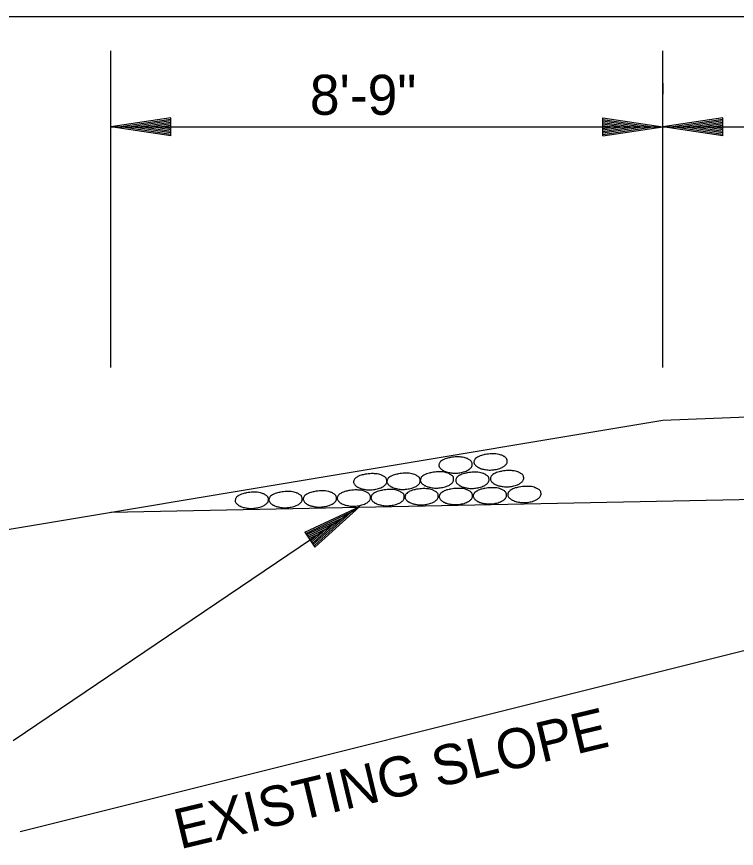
# Model space of a CAD drawing. Extents: x 634177 to 635904, y 289936 to 290970.
# Drawn here: x 635820.98 to 635831.78, y 290605.38 to 290617.85 of the extents above; entities that cross this region are included whole.
import ezdxf

# ---------------------------------------------------------------- set-up
doc = ezdxf.new("R2010")
doc.units = 0
doc.layers.add('Default', color=7, linetype='Continuous')

msp = doc.modelspace()

# ---------------------------------------------------------------- linework, layer by layer
at = {"layer": 'Default'}
for p, q in [((635808.678, 290617.846), (635838.678, 290617.846)), ((635822.398, 290612.588), (635822.398, 290617.336)), ((635830.678, 290612.588), (635830.678, 290617.336)), ((635830.679, 290616.686), (635830.679, 290616.848)), ((635823.298, 290616.328), (635822.398, 290616.193)), ((635823.298, 290616.306), (635822.548, 290616.193)), ((635823.298, 290616.058), (635823.298, 290616.328)), ((635829.778, 290616.328), (635830.678, 290616.193)), ((635829.778, 290616.058), (635829.778, 290616.328)), ((635829.778, 290616.306), (635830.528, 290616.193)), ((635831.578, 290616.328), (635830.678, 290616.193)), ((635831.578, 290616.306), (635830.828, 290616.193)), ((635831.578, 290616.058), (635831.578, 290616.328)), ((635822.398, 290616.193), (635838.678, 290616.193)), ((635823.298, 290616.058), (635822.398, 290616.193)), ((635823.298, 290616.081), (635822.548, 290616.193)), ((635823.298, 290616.283), (635822.703, 290616.193)), ((635823.298, 290616.103), (635822.703, 290616.193)), ((635823.298, 290616.26), (635822.853, 290616.193)), ((635823.298, 290616.127), (635822.853, 290616.193)), ((635823.298, 290616.237), (635823.006, 290616.193)), ((635823.298, 290616.15), (635823.006, 290616.193)), ((635823.298, 290616.215), (635823.156, 290616.193)), ((635823.298, 290616.172), (635823.156, 290616.193)), ((635829.778, 290616.283), (635830.373, 290616.193)), ((635829.778, 290616.26), (635830.223, 290616.193)), ((635829.778, 290616.237), (635830.07, 290616.193)), ((635829.778, 290616.215), (635829.92, 290616.193)), ((635829.778, 290616.058), (635830.678, 290616.193)), ((635829.778, 290616.15), (635830.07, 290616.193)), ((635829.778, 290616.103), (635830.373, 290616.193)), ((635829.778, 290616.081), (635830.528, 290616.193)), ((635829.778, 290616.127), (635830.223, 290616.193)), ((635829.778, 290616.172), (635829.92, 290616.193)), ((635831.578, 290616.058), (635830.678, 290616.193)), ((635831.578, 290616.081), (635830.828, 290616.193)), ((635831.578, 290616.283), (635830.983, 290616.193)), ((635831.578, 290616.103), (635830.983, 290616.193)), ((635831.578, 290616.26), (635831.133, 290616.193)), ((635831.578, 290616.127), (635831.133, 290616.193)), ((635831.578, 290616.237), (635831.285, 290616.193)), ((635831.578, 290616.15), (635831.285, 290616.193)), ((635831.578, 290616.215), (635831.436, 290616.193)), ((635831.578, 290616.172), (635831.436, 290616.193)), ((635836.678, 290612.034), (635830.678, 290611.794)), ((635830.678, 290611.794), (635808.678, 290608.128)), ((635838.678, 290610.74), (635822.398, 290610.414)), ((635825.308, 290610.118), (635826.132, 290610.504)), ((635825.458, 290609.894), (635826.132, 290610.504)), ((635825.32, 290610.1), (635826.007, 290610.421)), ((635825.333, 290610.081), (635825.878, 290610.335)), ((635825.432, 290609.931), (635825.878, 290610.335)), ((635825.445, 290609.912), (635826.007, 290610.421)), ((635825.346, 290610.062), (635825.753, 290610.252)), ((635825.42, 290609.95), (635825.753, 290610.252)), ((635825.308, 290610.118), (635825.458, 290609.894)), ((635825.359, 290610.042), (635825.626, 290610.168)), ((635825.371, 290610.024), (635825.501, 290610.085)), ((635825.394, 290609.988), (635825.501, 290610.085)), ((635825.407, 290609.969), (635825.626, 290610.168)), ((635832.678, 290608.537), (635821.036, 290605.627))]:
    msp.add_line(p, q, dxfattribs=at)
msp.add_lwpolyline([(635826.132, 290610.504), (635820.929, 290606.991)], dxfattribs=at)
for points in [[(635827.335, 290611.17), (635827.325, 290611.153), (635827.32, 290611.138), (635827.316, 290611.118), (635827.319, 290611.106), (635827.329, 290611.087), (635827.341, 290611.072), (635827.362, 290611.056), (635827.376, 290611.044), (635827.388, 290611.04), (635827.414, 290611.027), (635827.459, 290611.015), (635827.527, 290611.004), (635827.596, 290611.005), (635827.669, 290611.017), (635827.742, 290611.043), (635827.784, 290611.072), (635827.81, 290611.103), (635827.816, 290611.128), (635827.815, 290611.151), (635827.807, 290611.175), (635827.798, 290611.186), (635827.784, 290611.198), (635827.766, 290611.208), (635827.745, 290611.221), (635827.728, 290611.227), (635827.695, 290611.238), (635827.648, 290611.245), (635827.584, 290611.247), (635827.537, 290611.243), (635827.489, 290611.237), (635827.464, 290611.231), (635827.43, 290611.223), (635827.391, 290611.208), (635827.369, 290611.196), (635827.342, 290611.176), (635827.33, 290611.165)], [(635827.86, 290611.217), (635827.85, 290611.2), (635827.845, 290611.185), (635827.841, 290611.165), (635827.844, 290611.153), (635827.854, 290611.134), (635827.866, 290611.119), (635827.887, 290611.103), (635827.901, 290611.091), (635827.913, 290611.087), (635827.939, 290611.074), (635827.984, 290611.062), (635828.052, 290611.051), (635828.121, 290611.052), (635828.194, 290611.064), (635828.267, 290611.09), (635828.309, 290611.119), (635828.335, 290611.15), (635828.341, 290611.175), (635828.34, 290611.198), (635828.332, 290611.222), (635828.323, 290611.233), (635828.309, 290611.245), (635828.291, 290611.255), (635828.27, 290611.268), (635828.253, 290611.274), (635828.22, 290611.285), (635828.173, 290611.292), (635828.109, 290611.294), (635828.062, 290611.29), (635828.014, 290611.284), (635827.989, 290611.278), (635827.955, 290611.27), (635827.916, 290611.255), (635827.894, 290611.243), (635827.867, 290611.223), (635827.855, 290611.212)], [(635826.056, 290610.919), (635826.046, 290610.902), (635826.041, 290610.887), (635826.037, 290610.867), (635826.04, 290610.855), (635826.05, 290610.836), (635826.062, 290610.821), (635826.083, 290610.805), (635826.097, 290610.793), (635826.109, 290610.789), (635826.135, 290610.776), (635826.18, 290610.764), (635826.248, 290610.753), (635826.317, 290610.754), (635826.39, 290610.766), (635826.463, 290610.792), (635826.505, 290610.821), (635826.531, 290610.852), (635826.537, 290610.877), (635826.536, 290610.9), (635826.528, 290610.924), (635826.519, 290610.935), (635826.505, 290610.947), (635826.487, 290610.957), (635826.466, 290610.97), (635826.449, 290610.976), (635826.416, 290610.987), (635826.369, 290610.994), (635826.305, 290610.996), (635826.258, 290610.992), (635826.21, 290610.986), (635826.185, 290610.98), (635826.151, 290610.972), (635826.112, 290610.957), (635826.09, 290610.945), (635826.063, 290610.925), (635826.051, 290610.914)], [(635826.556, 290610.926), (635826.546, 290610.909), (635826.541, 290610.894), (635826.537, 290610.874), (635826.54, 290610.862), (635826.55, 290610.843), (635826.562, 290610.828), (635826.583, 290610.812), (635826.597, 290610.8), (635826.609, 290610.796), (635826.635, 290610.783), (635826.68, 290610.771), (635826.748, 290610.76), (635826.817, 290610.761), (635826.89, 290610.773), (635826.963, 290610.799), (635827.005, 290610.828), (635827.031, 290610.859), (635827.037, 290610.884), (635827.036, 290610.907), (635827.028, 290610.931), (635827.019, 290610.942), (635827.005, 290610.954), (635826.987, 290610.964), (635826.966, 290610.977), (635826.949, 290610.983), (635826.916, 290610.994), (635826.869, 290611.001), (635826.805, 290611.003), (635826.758, 290610.999), (635826.71, 290610.993), (635826.685, 290610.987), (635826.651, 290610.979), (635826.612, 290610.964), (635826.59, 290610.952), (635826.563, 290610.932), (635826.551, 290610.921)], [(635827.057, 290610.946), (635827.047, 290610.929), (635827.042, 290610.914), (635827.038, 290610.894), (635827.041, 290610.882), (635827.051, 290610.863), (635827.063, 290610.848), (635827.084, 290610.832), (635827.098, 290610.82), (635827.11, 290610.816), (635827.136, 290610.803), (635827.181, 290610.791), (635827.249, 290610.78), (635827.318, 290610.781), (635827.391, 290610.793), (635827.464, 290610.819), (635827.506, 290610.848), (635827.532, 290610.879), (635827.538, 290610.904), (635827.537, 290610.927), (635827.529, 290610.951), (635827.52, 290610.962), (635827.506, 290610.974), (635827.488, 290610.984), (635827.467, 290610.997), (635827.45, 290611.003), (635827.417, 290611.014), (635827.37, 290611.021), (635827.306, 290611.023), (635827.259, 290611.019), (635827.211, 290611.013), (635827.186, 290611.007), (635827.152, 290610.999), (635827.113, 290610.984), (635827.091, 290610.972), (635827.064, 290610.952), (635827.052, 290610.941)], [(635827.588, 290610.941), (635827.578, 290610.924), (635827.573, 290610.909), (635827.569, 290610.889), (635827.572, 290610.877), (635827.582, 290610.858), (635827.594, 290610.843), (635827.615, 290610.827), (635827.629, 290610.815), (635827.641, 290610.811), (635827.667, 290610.798), (635827.712, 290610.786), (635827.78, 290610.775), (635827.849, 290610.776), (635827.922, 290610.788), (635827.995, 290610.814), (635828.037, 290610.843), (635828.063, 290610.874), (635828.069, 290610.899), (635828.068, 290610.922), (635828.06, 290610.946), (635828.051, 290610.957), (635828.037, 290610.969), (635828.019, 290610.979), (635827.998, 290610.992), (635827.981, 290610.998), (635827.948, 290611.009), (635827.901, 290611.016), (635827.837, 290611.018), (635827.79, 290611.014), (635827.742, 290611.008), (635827.717, 290611.002), (635827.683, 290610.994), (635827.644, 290610.979), (635827.622, 290610.967), (635827.595, 290610.947), (635827.583, 290610.936)], [(635828.108, 290610.965), (635828.098, 290610.948), (635828.093, 290610.933), (635828.089, 290610.913), (635828.092, 290610.901), (635828.102, 290610.882), (635828.114, 290610.867), (635828.135, 290610.851), (635828.149, 290610.839), (635828.161, 290610.835), (635828.187, 290610.822), (635828.232, 290610.81), (635828.3, 290610.799), (635828.369, 290610.8), (635828.442, 290610.812), (635828.515, 290610.838), (635828.557, 290610.867), (635828.583, 290610.898), (635828.589, 290610.923), (635828.588, 290610.946), (635828.58, 290610.97), (635828.571, 290610.981), (635828.557, 290610.993), (635828.539, 290611.003), (635828.518, 290611.016), (635828.501, 290611.022), (635828.468, 290611.033), (635828.421, 290611.04), (635828.357, 290611.042), (635828.31, 290611.038), (635828.262, 290611.032), (635828.237, 290611.026), (635828.203, 290611.018), (635828.164, 290611.003), (635828.142, 290610.991), (635828.115, 290610.971), (635828.103, 290610.96)], [(635828.368, 290610.728), (635828.358, 290610.711), (635828.353, 290610.696), (635828.349, 290610.676), (635828.352, 290610.664), (635828.362, 290610.645), (635828.374, 290610.63), (635828.395, 290610.614), (635828.409, 290610.602), (635828.421, 290610.598), (635828.447, 290610.585), (635828.492, 290610.573), (635828.56, 290610.562), (635828.629, 290610.563), (635828.702, 290610.575), (635828.775, 290610.601), (635828.817, 290610.63), (635828.843, 290610.661), (635828.849, 290610.686), (635828.848, 290610.709), (635828.84, 290610.733), (635828.831, 290610.744), (635828.817, 290610.756), (635828.799, 290610.766), (635828.778, 290610.779), (635828.761, 290610.785), (635828.728, 290610.796), (635828.681, 290610.803), (635828.617, 290610.805), (635828.57, 290610.801), (635828.522, 290610.795), (635828.497, 290610.789), (635828.463, 290610.781), (635828.424, 290610.766), (635828.402, 290610.754), (635828.375, 290610.734), (635828.363, 290610.723)], [(635824.279, 290610.641), (635824.269, 290610.624), (635824.264, 290610.609), (635824.26, 290610.589), (635824.263, 290610.577), (635824.273, 290610.558), (635824.285, 290610.543), (635824.306, 290610.527), (635824.32, 290610.515), (635824.332, 290610.511), (635824.358, 290610.498), (635824.403, 290610.486), (635824.471, 290610.475), (635824.54, 290610.476), (635824.613, 290610.488), (635824.686, 290610.514), (635824.728, 290610.543), (635824.754, 290610.574), (635824.76, 290610.599), (635824.759, 290610.622), (635824.751, 290610.646), (635824.742, 290610.657), (635824.728, 290610.669), (635824.71, 290610.679), (635824.689, 290610.692), (635824.672, 290610.698), (635824.639, 290610.709), (635824.592, 290610.716), (635824.528, 290610.718), (635824.481, 290610.714), (635824.433, 290610.708), (635824.408, 290610.702), (635824.374, 290610.694), (635824.335, 290610.679), (635824.313, 290610.667), (635824.286, 290610.647), (635824.274, 290610.636)], [(635824.786, 290610.651), (635824.776, 290610.634), (635824.771, 290610.619), (635824.767, 290610.599), (635824.77, 290610.587), (635824.78, 290610.568), (635824.792, 290610.553), (635824.813, 290610.537), (635824.827, 290610.525), (635824.839, 290610.521), (635824.865, 290610.508), (635824.91, 290610.496), (635824.978, 290610.485), (635825.047, 290610.486), (635825.12, 290610.498), (635825.193, 290610.524), (635825.235, 290610.553), (635825.261, 290610.584), (635825.267, 290610.609), (635825.266, 290610.632), (635825.258, 290610.656), (635825.249, 290610.667), (635825.235, 290610.679), (635825.217, 290610.689), (635825.196, 290610.702), (635825.179, 290610.708), (635825.146, 290610.719), (635825.099, 290610.726), (635825.035, 290610.728), (635824.988, 290610.724), (635824.94, 290610.718), (635824.915, 290610.712), (635824.881, 290610.704), (635824.842, 290610.689), (635824.82, 290610.677), (635824.793, 290610.657), (635824.781, 290610.646)], [(635825.3, 290610.661), (635825.29, 290610.644), (635825.285, 290610.629), (635825.281, 290610.609), (635825.284, 290610.597), (635825.294, 290610.578), (635825.306, 290610.563), (635825.327, 290610.547), (635825.341, 290610.535), (635825.353, 290610.531), (635825.379, 290610.518), (635825.424, 290610.506), (635825.492, 290610.495), (635825.561, 290610.496), (635825.634, 290610.508), (635825.707, 290610.534), (635825.749, 290610.563), (635825.775, 290610.594), (635825.781, 290610.619), (635825.78, 290610.642), (635825.772, 290610.666), (635825.763, 290610.677), (635825.749, 290610.689), (635825.731, 290610.699), (635825.71, 290610.712), (635825.693, 290610.718), (635825.66, 290610.729), (635825.613, 290610.736), (635825.549, 290610.738), (635825.502, 290610.734), (635825.454, 290610.728), (635825.429, 290610.722), (635825.395, 290610.714), (635825.356, 290610.699), (635825.334, 290610.687), (635825.307, 290610.667), (635825.295, 290610.656)], [(635825.81, 290610.674), (635825.8, 290610.657), (635825.795, 290610.642), (635825.791, 290610.622), (635825.794, 290610.61), (635825.804, 290610.591), (635825.816, 290610.576), (635825.837, 290610.56), (635825.851, 290610.548), (635825.863, 290610.544), (635825.889, 290610.531), (635825.934, 290610.519), (635826.002, 290610.508), (635826.071, 290610.509), (635826.144, 290610.521), (635826.217, 290610.547), (635826.259, 290610.576), (635826.285, 290610.607), (635826.291, 290610.632), (635826.29, 290610.655), (635826.282, 290610.679), (635826.273, 290610.69), (635826.259, 290610.702), (635826.241, 290610.712), (635826.22, 290610.725), (635826.203, 290610.731), (635826.17, 290610.742), (635826.123, 290610.749), (635826.059, 290610.751), (635826.012, 290610.747), (635825.964, 290610.741), (635825.939, 290610.735), (635825.905, 290610.727), (635825.866, 290610.712), (635825.844, 290610.7), (635825.817, 290610.68), (635825.805, 290610.669)], [(635826.317, 290610.681), (635826.307, 290610.664), (635826.302, 290610.649), (635826.298, 290610.629), (635826.301, 290610.617), (635826.311, 290610.598), (635826.323, 290610.583), (635826.344, 290610.567), (635826.358, 290610.555), (635826.37, 290610.551), (635826.396, 290610.538), (635826.441, 290610.526), (635826.509, 290610.515), (635826.578, 290610.516), (635826.651, 290610.528), (635826.724, 290610.554), (635826.766, 290610.583), (635826.792, 290610.614), (635826.798, 290610.639), (635826.797, 290610.662), (635826.789, 290610.686), (635826.78, 290610.697), (635826.766, 290610.709), (635826.748, 290610.719), (635826.727, 290610.732), (635826.71, 290610.738), (635826.677, 290610.749), (635826.63, 290610.756), (635826.566, 290610.758), (635826.519, 290610.754), (635826.471, 290610.748), (635826.446, 290610.742), (635826.412, 290610.734), (635826.373, 290610.719), (635826.351, 290610.707), (635826.324, 290610.687), (635826.312, 290610.676)], [(635826.827, 290610.694), (635826.817, 290610.677), (635826.812, 290610.662), (635826.808, 290610.642), (635826.811, 290610.63), (635826.821, 290610.611), (635826.833, 290610.596), (635826.854, 290610.58), (635826.868, 290610.568), (635826.88, 290610.564), (635826.906, 290610.551), (635826.951, 290610.539), (635827.019, 290610.528), (635827.088, 290610.529), (635827.161, 290610.541), (635827.234, 290610.567), (635827.276, 290610.596), (635827.302, 290610.627), (635827.308, 290610.652), (635827.307, 290610.675), (635827.299, 290610.699), (635827.29, 290610.71), (635827.276, 290610.722), (635827.258, 290610.732), (635827.237, 290610.745), (635827.22, 290610.751), (635827.187, 290610.762), (635827.14, 290610.769), (635827.076, 290610.771), (635827.029, 290610.767), (635826.981, 290610.761), (635826.956, 290610.755), (635826.922, 290610.747), (635826.883, 290610.732), (635826.861, 290610.72), (635826.834, 290610.7), (635826.822, 290610.689)], [(635827.341, 290610.698), (635827.331, 290610.681), (635827.326, 290610.666), (635827.322, 290610.646), (635827.325, 290610.634), (635827.335, 290610.615), (635827.347, 290610.6), (635827.368, 290610.584), (635827.382, 290610.572), (635827.394, 290610.568), (635827.42, 290610.555), (635827.465, 290610.543), (635827.533, 290610.532), (635827.602, 290610.533), (635827.675, 290610.545), (635827.748, 290610.571), (635827.79, 290610.6), (635827.816, 290610.631), (635827.822, 290610.656), (635827.821, 290610.679), (635827.813, 290610.703), (635827.804, 290610.714), (635827.79, 290610.726), (635827.772, 290610.736), (635827.751, 290610.749), (635827.734, 290610.755), (635827.701, 290610.766), (635827.654, 290610.773), (635827.59, 290610.775), (635827.543, 290610.771), (635827.495, 290610.765), (635827.47, 290610.759), (635827.436, 290610.751), (635827.397, 290610.736), (635827.375, 290610.724), (635827.348, 290610.704), (635827.336, 290610.693)], [(635827.851, 290610.708), (635827.841, 290610.691), (635827.836, 290610.676), (635827.832, 290610.656), (635827.835, 290610.644), (635827.845, 290610.625), (635827.857, 290610.61), (635827.878, 290610.594), (635827.892, 290610.582), (635827.904, 290610.578), (635827.93, 290610.565), (635827.975, 290610.553), (635828.043, 290610.542), (635828.112, 290610.543), (635828.185, 290610.555), (635828.258, 290610.581), (635828.3, 290610.61), (635828.326, 290610.641), (635828.332, 290610.666), (635828.331, 290610.689), (635828.323, 290610.713), (635828.314, 290610.724), (635828.3, 290610.736), (635828.282, 290610.746), (635828.261, 290610.759), (635828.244, 290610.765), (635828.211, 290610.776), (635828.164, 290610.783), (635828.1, 290610.785), (635828.053, 290610.781), (635828.005, 290610.775), (635827.98, 290610.769), (635827.946, 290610.761), (635827.907, 290610.746), (635827.885, 290610.734), (635827.858, 290610.714), (635827.846, 290610.703)]]:
    msp.add_spline(points, degree=3, dxfattribs=at)

# ---------------------------------------------------------------- texts
msp.add_text('8\'-9"', height=0.6, dxfattribs=at).set_placement((635825.381, 290616.375))
msp.add_text('EXISTING SLOPE', height=0.60048, rotation=13.4637, dxfattribs=at).set_placement((635823.432, 290605.363))

doc.saveas('drawing.dxf')
